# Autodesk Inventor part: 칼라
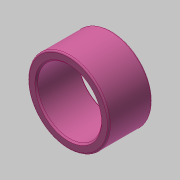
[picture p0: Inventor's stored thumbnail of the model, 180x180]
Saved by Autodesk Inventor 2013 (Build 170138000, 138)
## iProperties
Created: 2019-05
Part Number: 칼라
Material: 스테인리스강
Document SubType Name: Modeling
Designer: mduedu
Density: 1 g/cm^3
d0: 22.000 mm
d1: 28.000 mm
d2: 15.000 mm
d3: 0.00 deg
d4: 0.500 mm
d5: 0.500 mm
Author: mduedu
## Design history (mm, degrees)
sketch "스케치1"
  geometry: C1 r 11 at (0, 0); C2 r 14 at (0, 0); 1 further point
  constraints: 2 centre point, 2 coincident
  dimensions: "d0" = 22 diameter of C1; "d1" = 28 diameter of C2
extrude "돌출1" new body sketch "스케치1" distance "d2" = 15; taper "d3" = 0 deg
fillet "모깎기1" dims "d4" = 0.5
chamfer "모따기1" distance "d5" = 0.5; stored, may be unused: second distance "d6" = 2, angle "d7" = 45 deg
node "솔리드1"
